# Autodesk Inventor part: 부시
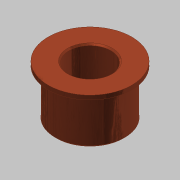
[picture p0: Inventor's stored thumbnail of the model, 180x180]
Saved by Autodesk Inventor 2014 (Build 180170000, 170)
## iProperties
Created: 2015-10
Part Number: 부시
Document SubType Name: Modeling
Designer: mdu
Density: 7.86 g/cm^3
Material: 강철, 연강
Mass: 246.97 g
Surface Area: 129.264 cm^2
Volume: 31.4212 cm^3
Appearance: 구리 - 새틴
Author: mdu
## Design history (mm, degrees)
sketch "스케치1"
  geometry: C1 r 31 at (0, 0) reference; C2 r 25 at (0, 0) reference; C3 r 30 at (0, 0) reference; 1 further point
  node "참조1"
  node "참조2"
  node "참조4"
extrude "돌출1" new body sketch "스케치1" distance "d0" = 3; taper "d1" = 0 deg
extrude "돌출2" join sketch "스케치1" distance "d2" = 36; taper "d3" = 0 deg
chamfer "모따기1" distance "d6" = 1; stored, may be unused: second distance "d7" = 2, angle "d8" = 45 deg
sketch "스케치3"
  geometry: C1 r 15 at (0, 0); 1 further point
  constraints: 1 centre point, 1 coincident
  dimensions: "d13" = 30 diameter of C1
extrude "돌출4" cut sketch "스케치3" stored distance "d14" = 10; taper "d15" = 0 deg
chamfer "모따기3" distance "d16" = 1; stored, may be unused: second distance "d17" = 2, angle "d18" = 45 deg
node "솔리드1"
